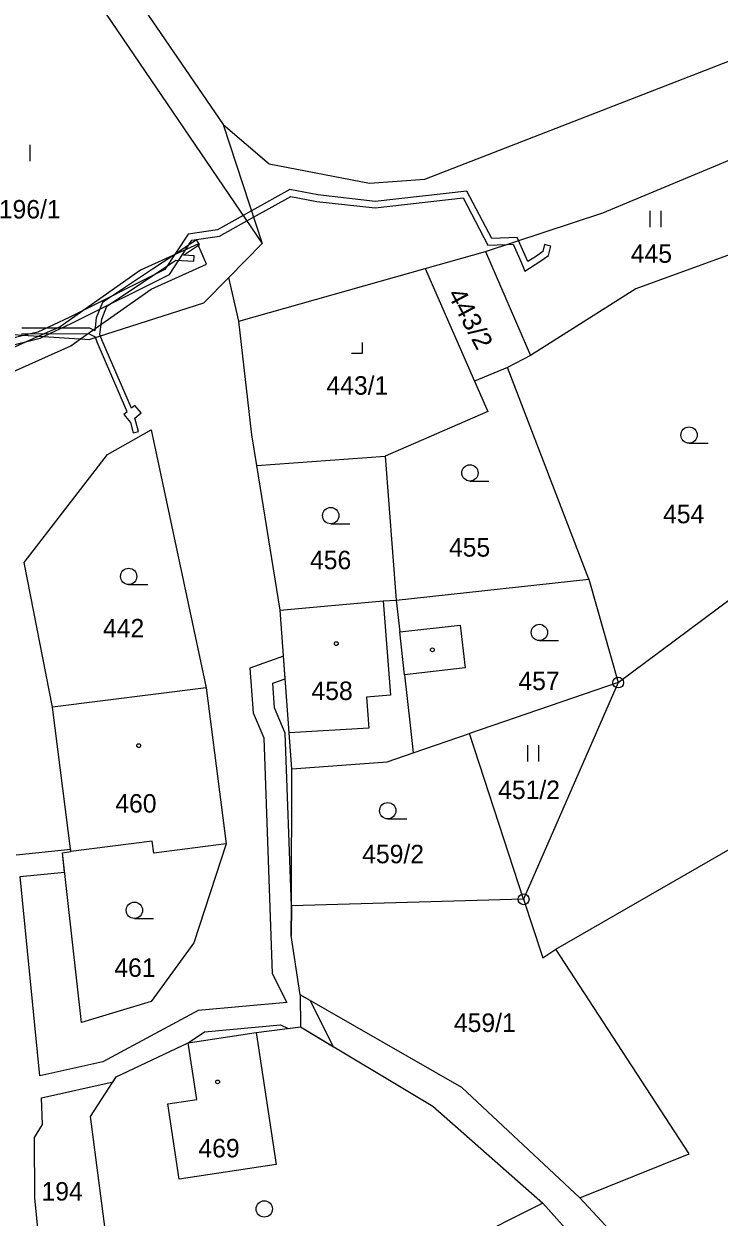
# Model space of a CAD drawing. Extents: x -727701 to -724405, y -960481 to -957284.
# Drawn here: x -726735.5 to -726671.5, y -958317.7 to -958207.9 of the extents above; entities that cross this region are included whole.
import ezdxf
from ezdxf.enums import TextEntityAlignment as Align

# ---------------------------------------------------------------- set-up
doc = ezdxf.new("R2010")
doc.units = 0
doc.header["$LTSCALE"] = 0.68
for name, color, linetype, lineweight in [('1', 7, 'Continuous', 25), ('13', 7, 'Continuous', 13), ('3', 7, 'Continuous', 25), ('4', 7, 'Continuous', 13), ('5', 7, 'Continuous', 25), ('8', 7, 'Continuous', 25)]:
    doc.layers.add(name, color=color, linetype=linetype, lineweight=lineweight)
doc.layers.add('2', color=7, linetype='Continuous')

msp = doc.modelspace()

# ---------------------------------------------------------------- linework, layer by layer
at = {"layer": '1'}
for p, q in [((-726739.72, -958184.25), (-726717.14, -958217.15)), ((-726733.51, -958198.77), (-726713.56, -958228.11)), ((-726698.6, -958222.18), (-726650.53, -958203.52)), ((-726717.14, -958217.15), (-726712.91, -958220.79)), ((-726717.14, -958217.15), (-726713.56, -958228.11)), ((-726682.22, -958225.29), (-726665.3, -958218.22)), ((-726712.91, -958220.79), (-726703.67, -958222.56)), ((-726703.67, -958222.56), (-726698.6, -958222.18)), ((-726693.01, -958228.83), (-726682.22, -958225.29)), ((-726713.56, -958228.11), (-726716.64, -958231.23)), ((-726698.55, -958230.4), (-726693.01, -958228.83)), ((-726693.01, -958228.83), (-726688.88, -958238.41)), ((-726670.49, -958229.12), (-726679.19, -958232.29)), ((-726715.69, -958235.26), (-726698.55, -958230.4)), ((-726698.55, -958230.4), (-726694.02, -958240.77)), ((-726716.64, -958231.23), (-726718.97, -958233.59)), ((-726715.69, -958235.26), (-726716.64, -958231.23)), ((-726679.19, -958232.29), (-726688.88, -958238.41)), ((-726718.97, -958233.59), (-726729.4, -958236.95)), ((-726757.07, -958235.13), (-726729.4, -958236.95)), ((-726714.5, -958245.7), (-726715.69, -958235.26)), ((-726688.88, -958238.41), (-726690.98, -958239.5)), ((-726690.98, -958239.5), (-726694.02, -958240.77)), ((-726683.5, -958259), (-726690.98, -958239.5)), ((-726694.02, -958240.77), (-726692.8, -958243.57)), ((-726692.8, -958243.57), (-726702.24, -958247.66)), ((-726727.78, -958247.52), (-726723.77, -958245.24)), ((-726723.77, -958245.24), (-726718.7, -958268.97)), ((-726714.05, -958248.52), (-726714.5, -958245.7)), ((-726735.47, -958257.47), (-726727.78, -958247.52)), ((-726714.05, -958248.52), (-726702.24, -958247.66)), ((-726702.24, -958247.66), (-726701.23, -958260.91)), ((-726711.91, -958261.83), (-726714.05, -958248.52)), ((-726680.8, -958268.5), (-726659.41, -958252.56)), ((-726732.85, -958270.77), (-726735.47, -958257.47)), ((-726701.23, -958260.91), (-726683.5, -958259)), ((-726683.5, -958259), (-726680.8, -958268.5)), ((-726711.91, -958261.83), (-726702.41, -958260.99)), ((-726702.41, -958260.99), (-726701.23, -958260.91)), ((-726701.23, -958260.91), (-726700.9, -958263.84)), ((-726711.07, -958273.13), (-726711.91, -958261.83)), ((-726700.9, -958263.84), (-726695.33, -958263.21)), ((-726695.33, -958263.21), (-726694.89, -958267.16)), ((-726686.53, -958293.04), (-726640.26, -958266.33)), ((-726694.89, -958267.16), (-726700.46, -958267.78)), ((-726700.46, -958267.78), (-726699.93, -958272.43)), ((-726718.7, -958268.97), (-726732.85, -958270.77)), ((-726718.7, -958268.97), (-726716.86, -958283.33)), ((-726680.8, -958268.5), (-726694.48, -958273.2)), ((-726680.8, -958268.5), (-726689.5, -958288.44)), ((-726731.15, -958284.05), (-726732.85, -958270.77)), ((-726710.82, -958276.45), (-726711.07, -958273.13)), ((-726699.93, -958272.43), (-726699.66, -958274.98)), ((-726699.66, -958274.98), (-726694.48, -958273.2)), ((-726689.5, -958288.44), (-726694.48, -958273.2)), ((-726702.05, -958275.8), (-726699.66, -958274.98)), ((-726710.87, -958289.03), (-726710.82, -958276.45)), ((-726710.82, -958276.45), (-726702.05, -958275.8)), ((-726723.67, -958283.1), (-726731.15, -958284.05)), ((-726723.53, -958284.19), (-726723.67, -958283.1)), ((-726731.94, -958284.15), (-726731.15, -958284.05)), ((-726730.17, -958299.76), (-726731.94, -958284.15)), ((-726716.86, -958283.33), (-726723.53, -958284.19)), ((-726716.86, -958283.33), (-726719.86, -958292.45)), ((-726689.5, -958288.44), (-726710.87, -958289.03)), ((-726689.5, -958288.44), (-726687.74, -958293.83)), ((-726710.87, -958289.03), (-726710.88, -958291.77)), ((-726710.06, -958297.22), (-726710.88, -958291.77)), ((-726719.86, -958292.45), (-726723.78, -958297.84)), ((-726687.74, -958293.83), (-726686.53, -958293.04)), ((-726674.26, -958311.86), (-726686.53, -958293.04)), ((-726695.18, -958305.74), (-726710.06, -958297.22)), ((-726723.78, -958297.84), (-726730.17, -958299.76)), ((-726720.37, -958301.63), (-726714.11, -958300.69)), ((-726714.11, -958300.69), (-726710.02, -958300.18)), ((-726714.11, -958300.69), (-726712.28, -958312.85)), ((-726726.99, -958304.77), (-726720.37, -958301.63)), ((-726719.58, -958306.87), (-726720.37, -958301.63)), ((-726729.36, -958308.42), (-726726.99, -958304.77)), ((-726684.33, -958315.89), (-726695.18, -958305.74)), ((-726722.24, -958307.27), (-726719.58, -958306.87)), ((-726721.2, -958314.19), (-726722.24, -958307.27)), ((-726697.85, -958307.47), (-726687.74, -958316.39)), ((-726727.9, -958319.49), (-726729.36, -958308.42)), ((-726684.33, -958315.89), (-726674.26, -958311.86)), ((-726712.28, -958312.85), (-726721.2, -958314.19)), ((-726684.33, -958315.89), (-726677.69, -958323.03)), ((-726687.74, -958316.39), (-726705.14, -958325.12)), ((-726687.74, -958316.39), (-726665.6, -958341))]:
    msp.add_line(p, q, dxfattribs=at)
msp.add_lwpolyline([(-726710.06, -958297.22), (-726710.02, -958300.18), (-726697.85, -958307.47)], dxfattribs=at)
at = {"layer": '13'}
for points in [[(-726738.78, -958238.02), (-726733.99, -958236.82), (-726733.67, -958236.67), (-726731.06, -958235.45), (-726722.08, -958230.96), (-726720.02, -958227.8), (-726717.48, -958227.43), (-726714.97, -958226.03), (-726714.35, -958225.68), (-726710.92, -958223.77), (-726708.53, -958224.24), (-726703.16, -958224.84), (-726695.07, -958223.92), (-726692.79, -958228.26), (-726691.08, -958228.2), (-726690.47, -958228.17), (-726689.74, -958229.83), (-726689.4, -958230.65), (-726688, -958229.77), (-726687.22, -958229.21), (-726686.99, -958228.36), (-726687.57, -958228.2), (-726687.74, -958228.85), (-726688.33, -958229.27), (-726689.11, -958229.77), (-726689.96, -958227.83), (-726690.08, -958227.56), (-726692.43, -958227.65), (-726694.73, -958223.28), (-726703.16, -958224.23), (-726708.44, -958223.64), (-726711.02, -958223.14), (-726714.54, -958225.1), (-726715.31, -958225.53), (-726717.67, -958226.85), (-726720.37, -958227.25), (-726722.5, -958230.5), (-726731.33, -958234.91), (-726734.19, -958236.25), (-726735.41, -958236.55), (-726738.83, -958237.41)], [(-726742.97, -958242.8), (-726731.16, -958237.51), (-726730.28, -958236.89), (-726723.77, -958232.31), (-726718.67, -958230), (-726719.49, -958228.18), (-726724.76, -958230.56), (-726732.15, -958235.76), (-726734.11, -958236.64), (-726744, -958241.07)], [(-726735.7, -958236.41), (-726729.55, -958236.4), (-726728.93, -958236.69), (-726728.9, -958236.79), (-726728.77, -958237.16), (-726726.06, -958243.42), (-726726.01, -958243.61), (-726726.28, -958243.84), (-726725.68, -958244.56), (-726725.43, -958245.52), (-726724.94, -958245.39), (-726725.26, -958244.17), (-726724.7, -958243.69), (-726725.26, -958243), (-726725.59, -958243.26), (-726728.31, -958236.98), (-726728.43, -958236.64), (-726728.48, -958236.48), (-726728.32, -958235.08), (-726727.86, -958233.87), (-726723.38, -958230.9), (-726721.49, -958229.65), (-726719.84, -958229.74), (-726719.82, -958229.24), (-726720.8, -958229.19), (-726719.32, -958228.19), (-726719.6, -958227.77), (-726721.7, -958229.19), (-726723.66, -958230.48), (-726728.26, -958233.55), (-726728.82, -958234.96), (-726728.94, -958236.13), (-726729.43, -958235.9), (-726735.66, -958235.91)], [(-726733.92, -958321.51), (-726734.49, -958315.91), (-726734.52, -958310.36), (-726733.78, -958309.15), (-726733.87, -958306.69), (-726727.28, -958305.22), (-726726.99, -958304.77), (-726720.37, -958301.63), (-726718.86, -958300.62), (-726711.86, -958299.98), (-726711.17, -958300.32), (-726710.02, -958300.18), (-726706.98, -958302), (-726709.15, -958297.74), (-726710.06, -958297.22), (-726710.88, -958291.77), (-726710.87, -958289.03), (-726711.43, -958273.15), (-726712.43, -958270.82), (-726712.59, -958268.56), (-726711.44, -958268.15), (-726711.59, -958266.08), (-726714.7, -958267.19), (-726714.4, -958271.3), (-726713.42, -958273.59), (-726712.65, -958295.26), (-726711.3, -958297.92), (-726719.45, -958298.66), (-726728.22, -958303.38), (-726734.01, -958304.67), (-726735.83, -958286.34), (-726731.74, -958285.93), (-726731.94, -958284.15), (-726731.15, -958284.05), (-726731.17, -958283.86), (-726736.2, -958284.37)]]:
    msp.add_lwpolyline(points, dxfattribs=at)
at = {"layer": '3'}
for p, q in [((-726734.92, -958220.54), (-726734.92, -958219.04)), ((-726677.861, -958226.6), (-726677.861, -958225.1)), ((-726676.86, -958226.6), (-726676.86, -958225.1)), ((-726674.283, -958246.48), (-726672.533, -958246.48)), ((-726694.443, -958249.96), (-726692.693, -958249.96)), ((-726707.253, -958253.89), (-726705.503, -958253.89)), ((-726725.843, -958259.48), (-726724.093, -958259.48)), ((-726688.053, -958264.64), (-726686.303, -958264.64)), ((-726689.101, -958275.76), (-726689.101, -958274.26)), ((-726688.1, -958275.76), (-726688.1, -958274.26)), ((-726702.003, -958281.04), (-726700.253, -958281.04)), ((-726725.313, -958290.2), (-726723.563, -958290.2))]:
    msp.add_line(p, q, dxfattribs=at)
msp.add_lwpolyline([(-726705.341, -958238.2), (-726704.34, -958238.2), (-726704.34, -958237.2)], dxfattribs=at)
for centre in [(-726674.2829, -958245.7298), (-726694.4429, -958249.2098), (-726707.2529, -958253.1398), (-726725.8429, -958258.7298), (-726688.0529, -958263.8898), (-726702.0029, -958280.2898), (-726725.3129, -958289.4498), (-726713.3629, -958316.9298)]:
    msp.add_circle(centre, 0.75, dxfattribs=at)
at = {"layer": '4'}
for p, q in [((-726702.41, -958260.99), (-726701.76, -958269.66)), ((-726700.46, -958267.78), (-726700.9, -958263.84)), ((-726701.76, -958269.66), (-726703.95, -958269.83)), ((-726703.95, -958269.83), (-726703.74, -958272.71)), ((-726703.74, -958272.71), (-726711.07, -958273.13))]:
    msp.add_line(p, q, dxfattribs=at)
at = {"layer": '5'}
for centre in [(-726706.7368, -958264.9192), (-726697.8968, -958265.4892), (-726724.9168, -958274.2992), (-726717.6568, -958305.2392)]:
    msp.add_circle(centre, 0.175, dxfattribs=at)
at = {"layer": '8'}
for centre, radius in [((-726680.8, -958268.4999), 0.5), ((-726680.8, -958268.4999), 0.0303), ((-726689.5, -958288.4399), 0.5), ((-726689.5, -958288.4399), 0.0303)]:
    msp.add_circle(centre, radius, dxfattribs=at)

# ---------------------------------------------------------------- texts
at = {"layer": '2'}
for s, p in [('196/1', (-726737.79, -958225.805)), ('445', (-726679.64, -958229.885)), ('454', (-726676.67, -958253.845)), ('455', (-726696.37, -958256.915)), ('442', (-726728.2, -958264.345)), ('457', (-726689.98, -958269.195)), ('458', (-726709.02, -958270.105)), ('460', (-726727.07, -958280.465)), ('461', (-726727.16, -958295.575)), ('469', (-726719.42, -958312.185)), ('194', (-726733.86, -958316.155))]:
    msp.add_text(s, height=1.7, dxfattribs=at).set_placement(p)
at = {"layer": '2', "width": 1.05}
msp.add_text('443/2', height=1.7, rotation=298, dxfattribs=at).set_placement((-726695.1464, -958235.4024), align=Align.CENTER)
at = {"layer": '2'}
for s, p in [('443/1', (-726704.8, -958242.015)), ('456', (-726707.259, -958258.075)), ('451/2', (-726689, -958279.215)), ('459/2', (-726701.51, -958285.125)), ('459/1', (-726693.07, -958300.645))]:
    msp.add_text(s, height=1.7, dxfattribs=at).set_placement(p, align=Align.CENTER)

doc.saveas('drawing.dxf')
